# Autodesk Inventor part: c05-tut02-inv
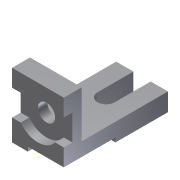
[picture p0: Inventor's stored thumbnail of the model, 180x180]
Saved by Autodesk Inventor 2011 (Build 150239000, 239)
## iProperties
Created: 2010-02
Part Number: c05-tut02-inv
Document SubType Name: Modeling
Designer: CADSoft
Density: 1 g/cm^3
Author: CADSoft
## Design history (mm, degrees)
sketch "Sketch1"
  geometry: 1 further point
sketch "Sketch2"
  geometry: L1 (0, 90)-(0, 0); L2 (0, 0)-(145, 0); L3 (145, 0)-(145, 25); L4 (145, 25)-(25, 25); L5 (25, 25)-(25, 90); L6 (25, 90)-(0, 90); 1 further point
  constraints: 12 end point, 1 coincident, 1 perpendicular, 1 other
  dimensions: "d0" = 90 distance of L1.start L1.end; "d1" = 25 distance of L5.end L1.start; "d2" = 145 distance of L1.end L2.end
extrude "Extrusion1" new body sketch "Sketch2" stored distance "d3" = 72; taper "d4" = 0 deg
sketch "Sketch3"
  geometry: L1 (0, 0)-(-6, -0.015); L2 (-6, -0.015)-(-6, 71.985); L3 (-6, 71.985)-(0, 72); L4 (0, 72)-(0, 0); L5 (0, 145)-(0, 0) reference
  constraints: 8 end point, 1 coincident, 1 point on line
  dimensions: "d5" = 72 distance of L3.end L1.start; "d6" = 6 distance of L1.start L1.end
extrude "Extrusion2" cut sketch "Sketch3" distance "d7" = 50; taper "d8" = 0 deg
sketch "Sketch4"
  geometry: L1 (72, -24)-(72, -60); L2 (0, -60)-(0, -24); L3 (0, -90)-(22, -90) reference; L4 (0, 0)-(0, -90) reference; L5 (72, -84)-(72, 0) reference; L6 (0, -24)-(12, -24); L7 (60, -24)-(72, -24); L8 (72, -60)-(60, -60); L9 (12, -60)-(0, -60); A1 r 30 centre (36, -42) between (12, -60) and (60, -60); A2 r 30 centre (36, -42) between (60, -24) and (12, -24)
  constraints: 12 end point, 4 point on circle, 2 centre point, 2 collinear, 1 concentric
  dimensions: "d10" = 48 distance from line of L3 A1.centre; "d11" = 36 distance from line of L4 A1.centre; "d14" = 30 radius of A2; "d15" = 36 distance of L2.start L2.end
extrude "Extrusion3" cut sketch "Sketch4" distance "d16" = 12; taper "d17" = 0 deg
sketch "Sketch5"
  geometry: C1 r 12 at (36, -42); A1 r 30 centre (36, -42) between (60, -24) and (12, -24) reference; 1 further point
  constraints: 1 centre point, 1 coincident
  dimensions: "d18" = 24 diameter of C1
extrude "Extrusion4" cut sketch "Sketch5" stored distance "d19" = 12; taper "d20" = 0 deg
sketch "Sketch6"
  geometry: L1 (24, 0)-(24, -50); L2 (48, -50)-(48, 0); L3 (48, 0)-(24, 0); L4 (72, 0)-(0, 0) reference; L5 (72, -120)-(72, 0) reference; A1 r 12 centre (36, -50) between (24, -50) and (48, -50); 1 further point
  constraints: 6 end point, 2 point on circle, 2 tangent, 2 vertical, 1 centre point, 1 collinear, 1 horizontal
  dimensions: "d21" = 50 distance of L2.start L2.end; "d22" = 12 radius of A1; "d23" = 36 distance from line of L5 A1.centre
extrude "Extrusion5" cut sketch "Sketch6" stored distance "d24" = 12; taper "d25" = 0 deg
body "Solid1"
